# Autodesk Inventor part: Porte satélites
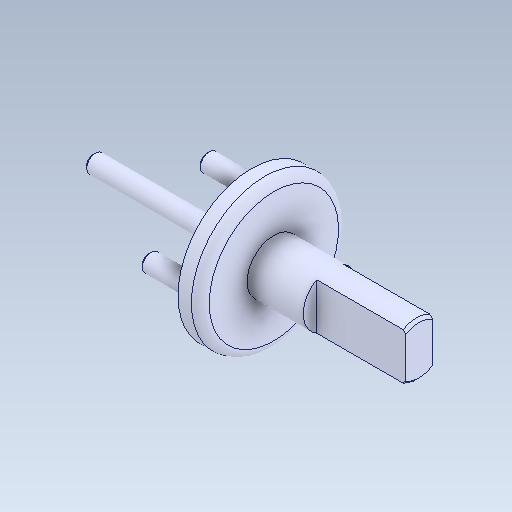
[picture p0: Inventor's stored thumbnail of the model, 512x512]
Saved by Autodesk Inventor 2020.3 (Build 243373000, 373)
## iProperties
Created: 2019-01
Part Number: Porte satélites
Material: Générique
Document SubType Name: Modeling
Designer: ficho
Density: 1 g/cm^3
Appearance: Par défaut
Mass: 0.991551 g
Surface Area: 10.5102 cm^2
Volume: 0.991551 cm^3
Sending System: SolidWorks 2015
Last Author: adrien
Last Saved: 2019-01-11
Author: ficho
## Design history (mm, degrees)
feature "Boss.-Extru.1"
sketch "Esquisse1"
  geometry: C1 r 8.25 at (0, 0) reference; C2 r 1 at (0, 0) reference; 1 further point
extrude "Extrusion1" cut sketch "Esquisse1" extent not by distance; stored distance "d0" = 17.8; taper "d1" = 0 deg
sketch "Esquisse2"
  geometry: C1 r 1 at (-6.5, 0); 1 further point
  constraints: 1 centre point
  dimensions: "d2" = 2 diameter of C1; "d3" = 6.5 distance of point (0, 0) C1.centre
extrude "Extrusion2" join sketch "Esquisse2" distance "d4" = 5; taper "d5" = 0 deg
chamfer "Chanfrein1" distance "d6" = 0.25; stored, may be unused: second distance "d7" = 2, angle "d8" = 45 deg
pattern_circular "Réseau circulaire1" dims angle "d10" = 360 deg
node "Solide1"
